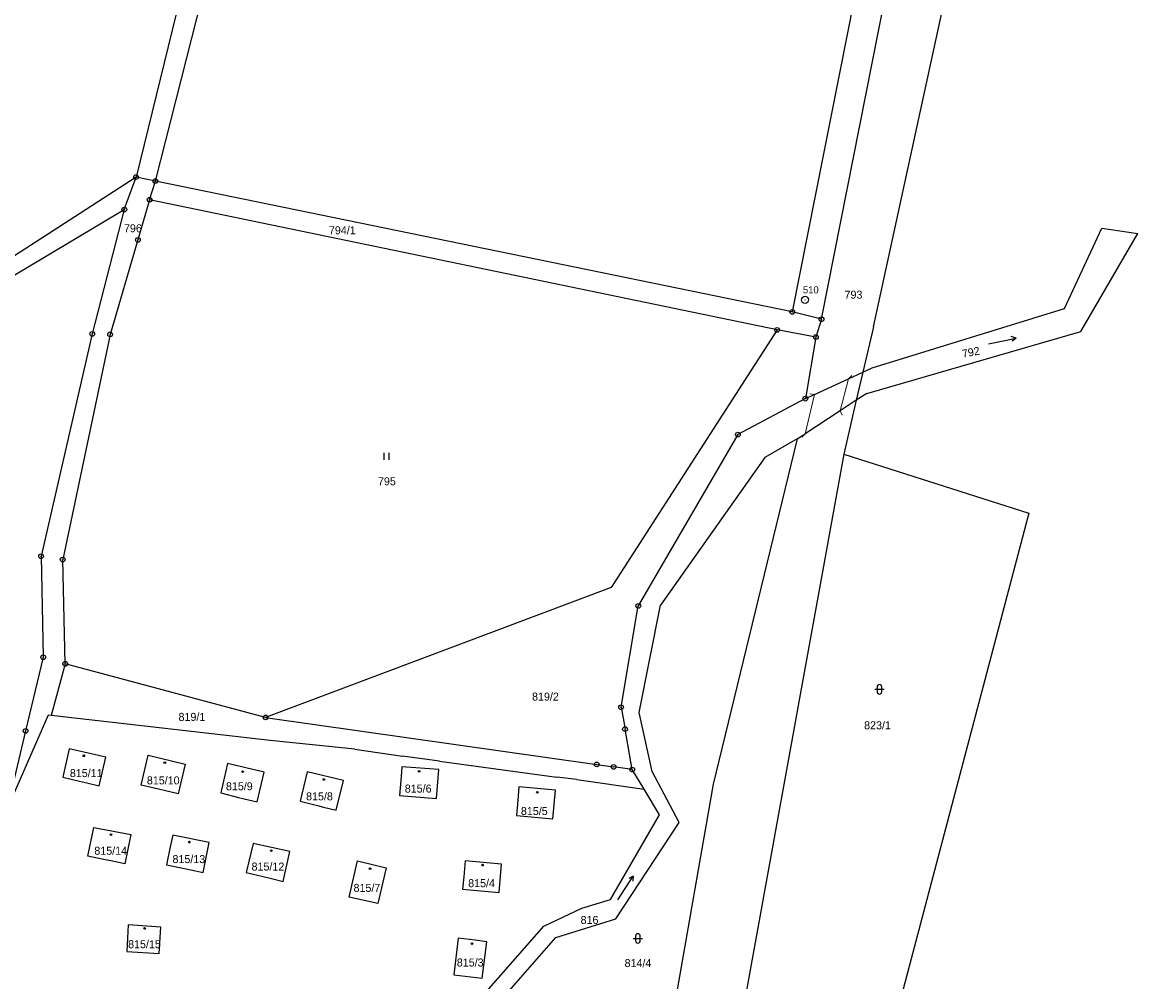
# Model space of a CAD drawing. Extents: x -727701 to -724405, y -960481 to -957284.
# Drawn here: x -727505.9 to -727269, y -959333.1 to -959129.4 of the extents above; entities that cross this region are included whole.
import ezdxf

# ---------------------------------------------------------------- set-up
doc = ezdxf.new("R2010")
doc.units = 0
doc.header["$LTSCALE"] = 0.68
for name, color, linetype, lineweight in [('1', 7, 'Continuous', 25), ('3', 7, 'Continuous', 25), ('4', 7, 'Continuous', 13), ('5', 7, 'Continuous', 25), ('8', 7, 'Continuous', 25)]:
    doc.layers.add(name, color=color, linetype=linetype, lineweight=lineweight)
doc.layers.add('2', color=7, linetype='Continuous')

msp = doc.modelspace()

# ---------------------------------------------------------------- linework, layer by layer
at = {"layer": '1'}
for p, q in [((-727269.64, -958824.07), (-727342.36, -959190.91)), ((-727336.15, -959192.47), (-727295.67, -958988.04)), ((-727477.62, -959163.13), (-727448.71, -959049.73)), ((-727459.94, -959073.68), (-727481.72, -959162.29)), ((-727325.13, -959194.05), (-727306.9, -959110.45)), ((-727481.72, -959162.29), (-727548.28, -959205.31)), ((-727484.21, -959169.2), (-727481.72, -959162.29)), ((-727477.62, -959163.13), (-727481.72, -959162.29)), ((-727478.84, -959167.09), (-727477.62, -959163.13)), ((-727342.36, -959190.91), (-727477.62, -959163.13)), ((-727478.84, -959167.09), (-727481.34, -959175.64)), ((-727345.57, -959194.73), (-727478.84, -959167.09)), ((-727558.7, -959213.52), (-727484.21, -959169.2)), ((-727484.21, -959169.2), (-727491.03, -959195.59)), ((-727284.54, -959190.16), (-727276.59, -959173.14)), ((-727276.59, -959173.14), (-727269, -959174.26)), ((-727281.08, -959195.1), (-727269, -959174.26)), ((-727481.34, -959175.64), (-727487.22, -959195.7)), ((-727336.15, -959192.47), (-727342.36, -959190.91)), ((-727325.37, -959202.79), (-727284.54, -959190.16)), ((-727336.15, -959192.47), (-727337.35, -959196.25)), ((-727325.13, -959194.05), (-727327.38, -959203.71)), ((-727491.03, -959195.59), (-727501.9, -959242.8)), ((-727487.22, -959195.7), (-727497.3, -959243.5)), ((-727345.57, -959194.73), (-727380.83, -959249.41)), ((-727337.35, -959196.25), (-727345.57, -959194.73)), ((-727337.35, -959196.25), (-727339.58, -959209.33)), ((-727326.55, -959208.23), (-727281.08, -959195.1)), ((-727330.42, -959205.11), (-727327.38, -959203.71)), ((-727327.38, -959203.71), (-727328.77, -959209.68)), ((-727327.38, -959203.71), (-727325.37, -959202.79)), ((-727337.66, -959208.45), (-727330.42, -959205.11)), ((-727339.58, -959209.33), (-727337.66, -959208.45)), ((-727326.55, -959208.23), (-727328.77, -959209.68)), ((-727339.58, -959209.33), (-727353.89, -959216.94)), ((-727328.77, -959209.68), (-727332.21, -959211.93)), ((-727328.77, -959209.68), (-727331.42, -959221.09)), ((-727332.21, -959211.93), (-727339.63, -959216.78)), ((-727353.89, -959216.94), (-727375.05, -959253.34)), ((-727341.34, -959217.89), (-727359.19, -959291.2)), ((-727341.34, -959217.89), (-727348.21, -959221.84)), ((-727341.34, -959217.89), (-727339.63, -959216.78)), ((-727348.21, -959221.84), (-727370.32, -959253.17)), ((-727331.42, -959221.09), (-727344.75, -959294.36)), ((-727331.42, -959221.09), (-727292.14, -959233.61)), ((-727292.14, -959233.61), (-727328.4, -959371.05)), ((-727501.9, -959242.8), (-727501.43, -959264.23)), ((-727496.75, -959265.63), (-727497.3, -959243.5)), ((-727380.83, -959249.41), (-727454.2, -959277)), ((-727378.72, -959274.86), (-727375.05, -959253.34)), ((-727374.86, -959275.99), (-727370.32, -959253.17)), ((-727501.43, -959264.23), (-727505.17, -959279.87)), ((-727496.75, -959265.63), (-727499.72, -959276.58)), ((-727454.2, -959277), (-727496.75, -959265.63)), ((-727378.72, -959274.86), (-727377.88, -959279.5)), ((-727500.39, -959276.5), (-727507.58, -959293)), ((-727499.72, -959276.58), (-727500.39, -959276.5)), ((-727453.22, -959281.91), (-727499.72, -959276.58)), ((-727454.2, -959277), (-727383.89, -959287)), ((-727372.09, -959288.46), (-727374.86, -959275.99)), ((-727376.33, -959288.07), (-727377.88, -959279.5)), ((-727505.17, -959279.87), (-727508.38, -959293.4)), ((-727435.24, -959283.78), (-727453.22, -959281.91)), ((-727495.94, -959283.67), (-727497.3, -959289.7)), ((-727488.13, -959285.44), (-727495.94, -959283.67)), ((-727435.24, -959283.78), (-727425.12, -959285.23)), ((-727489.56, -959291.55), (-727488.13, -959285.44)), ((-727480.65, -959291.37), (-727479.18, -959285.03)), ((-727479.18, -959285.03), (-727471.31, -959286.91)), ((-727462.32, -959286.82), (-727463.73, -959293.05)), ((-727454.54, -959288.62), (-727462.32, -959286.82)), ((-727417.25, -959286.3), (-727425.12, -959285.23)), ((-727417.25, -959286.3), (-727400.12, -959288.66)), ((-727471.31, -959286.91), (-727472.76, -959293.25)), ((-727456, -959294.94), (-727454.54, -959288.62)), ((-727445.41, -959288.55), (-727446.88, -959294.81)), ((-727437.69, -959290.42), (-727445.41, -959288.55)), ((-727425.29, -959287.48), (-727425.44, -959289.58)), ((-727417.39, -959288.06), (-727425.29, -959287.48)), ((-727417.9, -959294.23), (-727417.39, -959288.06)), ((-727400.12, -959288.66), (-727392.34, -959289.72)), ((-727383.89, -959287), (-727380.3, -959287.51)), ((-727376.33, -959288.07), (-727380.3, -959287.51)), ((-727373.82, -959292.23), (-727376.33, -959288.07)), ((-727366.37, -959299.31), (-727372.09, -959288.46)), ((-727497.3, -959289.7), (-727493.74, -959290.55)), ((-727493.74, -959290.55), (-727492.47, -959290.85)), ((-727492.47, -959290.85), (-727489.56, -959291.55)), ((-727476.93, -959292.26), (-727480.65, -959291.37)), ((-727439.21, -959296.72), (-727437.69, -959290.42)), ((-727425.44, -959289.58), (-727425.74, -959293.58)), ((-727388.09, -959290.17), (-727392.34, -959289.72)), ((-727388.09, -959290.17), (-727373.82, -959292.23)), ((-727359.19, -959291.2), (-727369.06, -959347.75)), ((-727475.76, -959292.54), (-727476.93, -959292.26)), ((-727472.76, -959293.25), (-727475.76, -959292.54)), ((-727463.73, -959293.05), (-727459.94, -959293.98)), ((-727459.94, -959293.98), (-727458.75, -959294.27)), ((-727425.74, -959293.58), (-727417.9, -959294.23)), ((-727400.4, -959291.77), (-727400.65, -959294.61)), ((-727392.61, -959292.45), (-727400.4, -959291.77)), ((-727393.22, -959298.55), (-727392.61, -959292.45)), ((-727370.52, -959297.69), (-727373.82, -959292.23)), ((-727458.75, -959294.27), (-727456, -959294.94)), ((-727446.88, -959294.81), (-727443.2, -959295.72)), ((-727443.2, -959295.72), (-727441.93, -959296.04)), ((-727441.93, -959296.04), (-727439.21, -959296.72)), ((-727400.65, -959294.61), (-727400.93, -959297.81)), ((-727344.75, -959294.36), (-727355.02, -959350.92)), ((-727400.93, -959297.81), (-727393.22, -959298.55)), ((-727380.95, -959315.67), (-727370.52, -959297.69)), ((-727491.98, -959306.47), (-727490.68, -959300.35)), ((-727490.68, -959300.35), (-727482.84, -959301.89)), ((-727379.8, -959319.78), (-727366.37, -959299.31)), ((-727482.84, -959301.89), (-727484.1, -959308.06)), ((-727473.92, -959301.98), (-727474.44, -959304.49)), ((-727466.2, -959303.54), (-727473.92, -959301.98)), ((-727474.44, -959304.49), (-727475.22, -959308.3)), ((-727467.47, -959309.9), (-727466.2, -959303.54)), ((-727456.83, -959303.77), (-727458.3, -959309.9)), ((-727449.06, -959305.49), (-727456.83, -959303.77)), ((-727450.5, -959311.83), (-727449.06, -959305.49)), ((-727488.27, -959307.22), (-727491.98, -959306.47)), ((-727487.05, -959307.47), (-727488.27, -959307.22)), ((-727484.1, -959308.06), (-727487.05, -959307.47)), ((-727436.47, -959315.18), (-727434.69, -959307.49)), ((-727434.69, -959307.49), (-727433.55, -959307.76)), ((-727433.55, -959307.76), (-727432.1, -959308.1)), ((-727432.1, -959308.1), (-727428.63, -959308.92)), ((-727411.82, -959307.46), (-727412.13, -959310.88)), ((-727404.08, -959308.13), (-727411.82, -959307.46)), ((-727404.61, -959314.2), (-727404.08, -959308.13)), ((-727475.22, -959308.3), (-727471.79, -959309.01)), ((-727471.79, -959309.01), (-727470.05, -959309.37)), ((-727470.05, -959309.37), (-727467.47, -959309.9)), ((-727458.3, -959309.9), (-727454.7, -959310.79)), ((-727428.63, -959308.92), (-727430.39, -959316.53)), ((-727454.7, -959310.79), (-727452.96, -959311.22)), ((-727452.96, -959311.22), (-727450.5, -959311.83)), ((-727412.13, -959310.88), (-727412.37, -959313.5)), ((-727430.39, -959316.53), (-727436.47, -959315.18)), ((-727412.37, -959313.5), (-727404.61, -959314.2)), ((-727395.09, -959321.33), (-727387.06, -959317.49)), ((-727387.06, -959317.49), (-727380.95, -959315.67)), ((-727392.56, -959323.74), (-727379.8, -959319.78)), ((-727483.36, -959321.07), (-727483.71, -959326.69)), ((-727476.48, -959321.52), (-727483.36, -959321.07)), ((-727476.8, -959327.11), (-727476.48, -959321.52)), ((-727408.27, -959336.35), (-727395.09, -959321.33)), ((-727413.31, -959323.88), (-727414.25, -959331.69)), ((-727409.68, -959324.33), (-727413.31, -959323.88)), ((-727407.21, -959324.63), (-727409.68, -959324.33)), ((-727408.22, -959332.38), (-727407.21, -959324.63)), ((-727405.74, -959338.75), (-727392.56, -959323.74)), ((-727483.71, -959326.69), (-727476.8, -959327.11)), ((-727414.25, -959331.69), (-727408.22, -959332.38))]:
    msp.add_line(p, q, dxfattribs=at)
at = {"layer": '3'}
for p, q in [((-727294.817, -959196.451), (-727295.669, -959197.145)), ((-727429.001, -959222.32), (-727429.001, -959220.82)), ((-727428, -959222.32), (-727428, -959220.82)), ((-727324.841, -959271.041), (-727322.839, -959271.041)), ((-727324.341, -959270.541), (-727324.341, -959271.542)), ((-727323.339, -959271.542), (-727323.339, -959270.541)), ((-727376.14, -959310.684), (-727376.251, -959311.777)), ((-727376.141, -959323.921), (-727374.139, -959323.921)), ((-727375.641, -959323.421), (-727375.641, -959324.422)), ((-727374.639, -959324.422), (-727374.639, -959323.421))]:
    msp.add_line(p, q, dxfattribs=at)
for points in [[(-727300.686, -959197.699), (-727294.817, -959196.451), (-727295.877, -959196.164)], [(-727379.407, -959315.716), (-727376.14, -959310.684), (-727377.092, -959311.231)]]:
    msp.add_lwpolyline(points, dxfattribs=at)
for centre, start, end in [((-727323.84, -959270.5409), 0, 180), ((-727323.84, -959271.5409), 180, 359.98789), ((-727375.14, -959323.4209), 0, 180), ((-727375.14, -959324.4209), 180, 359.98789)]:
    msp.add_arc(centre, 0.5, start, end, dxfattribs=at)
at = {"layer": '4'}
for p, q in [((-727330.42, -959205.11), (-727332.21, -959211.93)), ((-727329.676, -959204.441), (-727330.419, -959205.11)), ((-727337.66, -959208.45), (-727339.63, -959216.78)), ((-727338.645, -959208.276), (-727337.66, -959208.449)), ((-727331.788, -959212.837), (-727332.21, -959211.931)), ((-727340.338, -959217.487), (-727339.631, -959216.78))]:
    msp.add_line(p, q, dxfattribs=at)
at = {"layer": '5'}
for centre in [(-727492.8068, -959285.1592), (-727475.6168, -959286.6292), (-727459.0868, -959288.5292), (-727421.5968, -959288.4692), (-727441.8368, -959290.1892), (-727396.5068, -959292.9092), (-727487.0468, -959301.8692), (-727470.3868, -959303.4892), (-727452.9868, -959305.3092), (-727408.1068, -959308.3692), (-727432.0168, -959309.1292), (-727479.8768, -959321.8092), (-727410.3868, -959325.0592)]:
    msp.add_circle(centre, 0.175, dxfattribs=at)
at = {"layer": '8'}
for centre, radius in [((-727481.72, -959162.2899), 0.5), ((-727481.72, -959162.2899), 0.0303), ((-727477.62, -959163.1299), 0.5), ((-727477.62, -959163.1299), 0.0303), ((-727478.84, -959167.0899), 0.5), ((-727478.84, -959167.0899), 0.0303), ((-727484.21, -959169.1999), 0.5), ((-727484.21, -959169.1999), 0.0303), ((-727481.34, -959175.6399), 0.5), ((-727481.34, -959175.6399), 0.0303), ((-727339.64, -959188.3498), 0.75), ((-727339.64, -959188.3498), 0.03), ((-727342.36, -959190.9099), 0.5), ((-727342.36, -959190.9099), 0.0303), ((-727336.15, -959192.4699), 0.5), ((-727345.57, -959194.7299), 0.5), ((-727336.15, -959192.4699), 0.0303), ((-727491.03, -959195.5899), 0.5), ((-727491.03, -959195.5899), 0.0303), ((-727487.22, -959195.6999), 0.5), ((-727487.22, -959195.6999), 0.0303), ((-727345.57, -959194.7299), 0.0303), ((-727337.35, -959196.2499), 0.5), ((-727337.35, -959196.2499), 0.0303), ((-727339.58, -959209.3299), 0.5), ((-727339.58, -959209.3299), 0.0303), ((-727353.89, -959216.9399), 0.5), ((-727353.89, -959216.9399), 0.0303), ((-727501.9, -959242.7999), 0.5), ((-727501.9, -959242.7999), 0.0303), ((-727497.3, -959243.4999), 0.5), ((-727497.3, -959243.4999), 0.0303), ((-727375.05, -959253.3399), 0.5), ((-727375.05, -959253.3399), 0.0303), ((-727501.43, -959264.2299), 0.5), ((-727501.43, -959264.2299), 0.0303), ((-727496.75, -959265.6299), 0.5), ((-727496.75, -959265.6299), 0.0303), ((-727378.72, -959274.8599), 0.5), ((-727378.72, -959274.8599), 0.0303), ((-727454.2, -959276.9999), 0.5), ((-727454.2, -959276.9999), 0.0303), ((-727505.17, -959279.8699), 0.5), ((-727377.88, -959279.4999), 0.5), ((-727377.88, -959279.4999), 0.0303), ((-727505.17, -959279.8699), 0.0303), ((-727383.89, -959286.9999), 0.5), ((-727383.89, -959286.9999), 0.0303), ((-727380.3, -959287.5099), 0.5), ((-727380.3, -959287.5099), 0.0303), ((-727376.33, -959288.0699), 0.5), ((-727376.33, -959288.0699), 0.0303)]:
    msp.add_circle(centre, radius, dxfattribs=at)

# ---------------------------------------------------------------- texts
at = {"layer": '2'}
for s, p in [('796', (-727484.28, -959174.005)), ('794/1', (-727440.76, -959174.425)), ('793', (-727331.26, -959188.095)), ('795', (-727430.34, -959227.725)), ('819/2', (-727397.62, -959273.435)), ('819/1', (-727472.7, -959277.745)), ('823/1', (-727327.1, -959279.525)), ('815/11', (-727495.78, -959289.675)), ('815/10', (-727479.42, -959291.225)), ('815/9', (-727462.63, -959292.475)), ('815/6', (-727424.65, -959292.965)), ('815/8', (-727445.61, -959294.615)), ('815/5', (-727399.99, -959297.735)), ('815/14', (-727490.58, -959306.165)), ('815/13', (-727473.98, -959307.935)), ('815/12', (-727457.19, -959309.525)), ('815/7', (-727435.53, -959314.045)), ('815/4', (-727411.19, -959313.045)), ('816', (-727387.31, -959320.855)), ('815/15', (-727483.41, -959326.005)), ('815/3', (-727413.6, -959329.895)), ('814/4', (-727377.97, -959330.015))]:
    msp.add_text(s, height=1.7, dxfattribs=at).set_placement(p)
msp.add_text('792', height=1.7, rotation=11, dxfattribs=at).set_placement((-727306.128, -959200.667))
at = {"layer": '8'}
msp.add_text('510', height=1.5, dxfattribs=at).set_placement((-727340.1, -959186.975))

doc.saveas('drawing.dxf')
